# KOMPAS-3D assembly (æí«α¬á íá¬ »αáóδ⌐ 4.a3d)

Referenced files in D:\АСКОН работа\Конкурс HOME\06_Сюваев_Сборная модель танка Т90\ДЕТАЛИ\КОРПУС\МЕТАЛЛ\КОРПУС ШТАМПОВКА\БАКИ\: бак правый 4.m3d
Referenced files in D:\АСКОН работа\Конкурс HOME\06_Сюваев_Сборная модель танка Т90\ДЕТАЛИ\ОБЩИЕ ДЕТАЛИ\: ручки баков.m3d
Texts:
  Сборка бак правый 4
